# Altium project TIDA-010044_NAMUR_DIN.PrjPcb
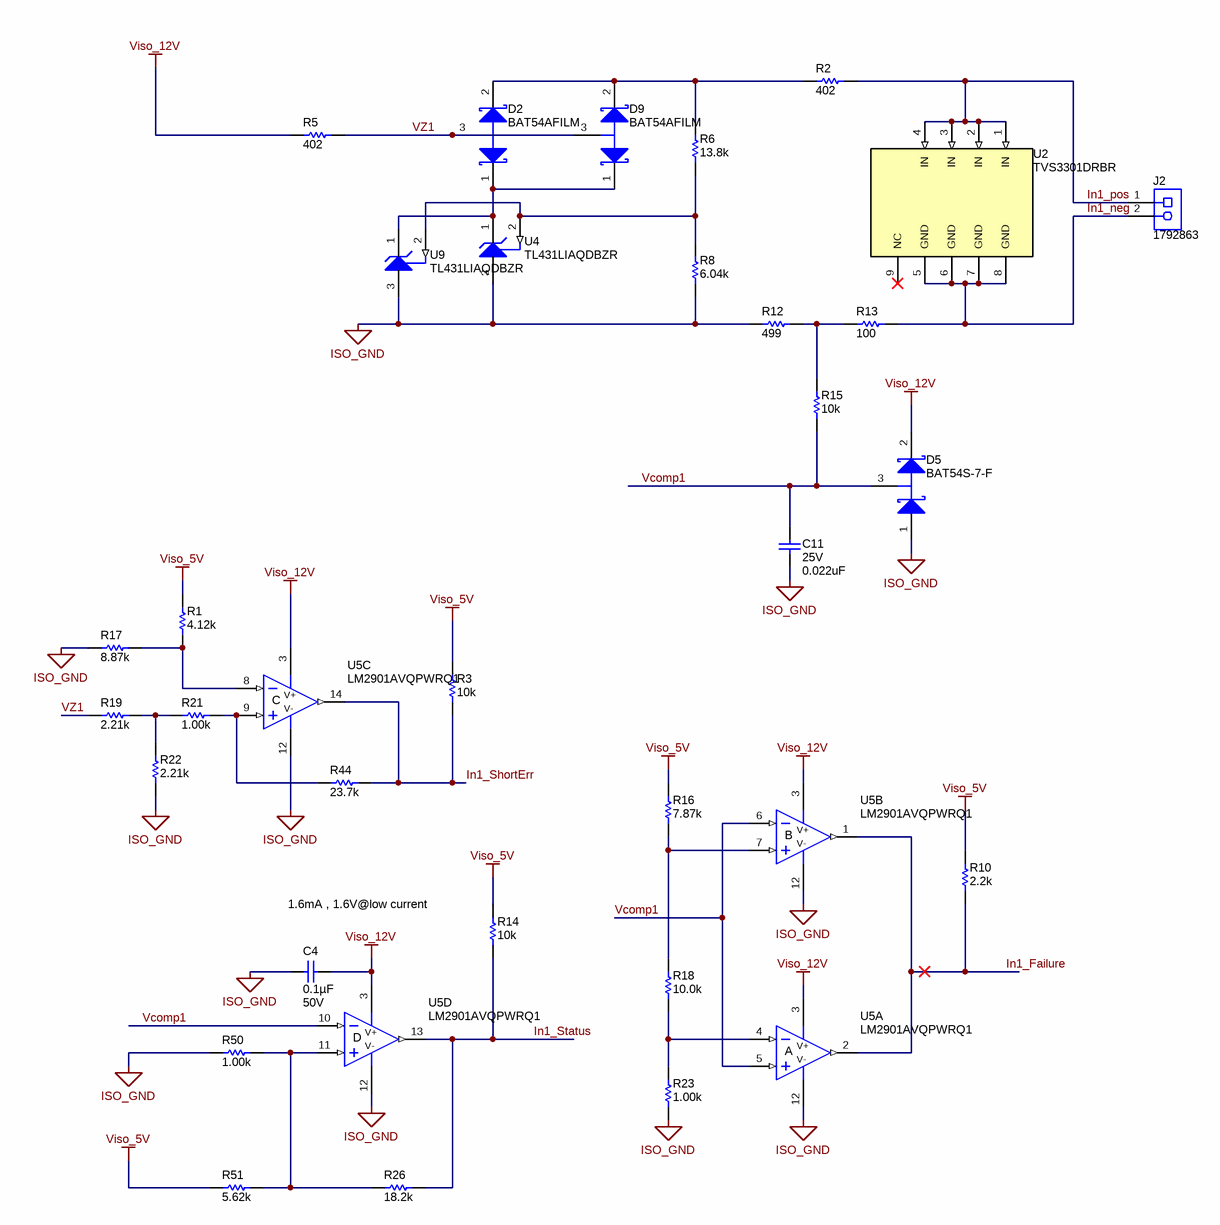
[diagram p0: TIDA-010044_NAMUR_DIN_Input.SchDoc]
CopyrightYear: 2018; PCB_Layout: Ahmed Noeman; PCB_Rev: A; PRJ_Customer: Public Release; PRJ_Engineer: Ahmed Noeman; PRJ_Number: TIDA-010044; PRJ_Title: NAMUR PLC digital input; SCH_Rev: A; TechSupport: http://www.ti.com/support; TID: TIDA-010044
4 sheets, 86 parts. Net scope: global (net labels, ports and power ports of the same name join across sheets).
Board file: TIDA-010044_NAMUR_DIN_PCB.PcbDoc
Sheets:
  TIDA-010044_NAMUR_DIN_Input.SchDoc
  TIDA-010044_NAMUR_DIN_CoverSheet.SchDoc
  TIDA-010044_NAMUR_DIN_Hardware.SchDoc
  TIDA-010044_NAMUR_DIN_Power.SchDoc

## Sheet TIDA-010044_NAMUR_DIN_Input.SchDoc: NAMUR DIN Input Stage
size 431 x 279 mm; Date: Not shown in title block; ApprovedBy: Not shown in title block; CheckedBy: Not shown in title block; Author: Not shown in title block; CompanyName: Not shown in title block; Engineer: Not shown in title block; Organization: Not shown in title block; Address1: Not shown in title block; Address2: Not shown in title block; Address3: Not shown in title block; Address4: Not shown in title block; DocumentNumber: 1; Revision: Use project parameter SCH_Rev; SheetNumber: 3; SheetTotal: 4; PageSetup: Record=PageOptions¦CenterHorizontal=True¦CenterVertical=True¦PrintScale=1.00¦XCorrection=1.00¦YCorrection=1.00¦PrintKind=0¦BorderSize=5000000¦LeftOffset=0¦BottomOffset=0¦Orientation=2¦PaperLength=1000¦PaperWidth=1000¦Scale=100¦PaperSource=15¦PrintQuality=600¦MediaType=1¦DitherType=10¦PaperKind=Letter¦PrintScaleMode=1

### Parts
C4  ValueDisplayed: 0.1µF  VDC_V: 50V  [0603]  (hidden comment: 06035C104JAT2A)
C11  VDC_V: 25V  ValueDisplayed: 0.022uF  [0603]  (hidden comment: C0603C223K3RACTU)
D2  BAT54AFILM  [SOT-23]
D5  BAT54S-7-F  [SOT-23]
D9  BAT54AFILM  [SOT-23]
J2  1792863  [Phoenix_1792863]
R1  ValueDisplayed: 4.12k  [0603]  (hidden comment: RT0603BRD074K12L)
R2  ValueDisplayed: 402  [MMB0207]  (hidden comment: MMB02070C4020FB200)
R3  ValueDisplayed: 10k  [0603]  (hidden comment: RC1608J103CS)
R5  ValueDisplayed: 402  [MMB0207]  (hidden comment: MMB02070C4020FB200)
R6  ValueDisplayed: 13.8k  [0603]  (hidden comment: RT0603BRD0713K8L)
R8  ValueDisplayed: 6.04k  [0603]  (hidden comment: RT0603DRE076K04L)
R10  ValueDisplayed: 2.2k  [0603]  (hidden comment: RC0603JR-072K2L)
R12  ValueDisplayed: 499  [MMB0207]  (hidden comment: MMB02070C4990FB200)
R13  ValueDisplayed: 100  [MMB0207]  (hidden comment: CMB02070X1000GB200)
R14  ValueDisplayed: 10k  [0603]  (hidden comment: RC1608J103CS)
R15  ValueDisplayed: 10k  [0603]  (hidden comment: RC1608J103CS)
R16  ValueDisplayed: 7.87k  [0603]  (hidden comment: RG1608P-7871-B-T5)
R17  ValueDisplayed: 8.87k  [0603]  (hidden comment: RT0603BRD078K87L)
R18  ValueDisplayed: 10.0k  [TNPW0603]  (hidden comment: TNPW060310K0BEEA)
R19  ValueDisplayed: 2.21k  [0603]  (hidden comment: RT0603BRD072K21L)
R21  ValueDisplayed: 1.00k  [0603]  (hidden comment: RT0603BRD071KL)
R22  ValueDisplayed: 2.21k  [0603]  (hidden comment: RT0603BRD072K21L)
R23  ValueDisplayed: 1.00k  [0603]  (hidden comment: RT0603BRD071KL)
R26  ValueDisplayed: 18.2k  [0603]  (hidden comment: ERA-3AEB1822V)
R44  ValueDisplayed: 23.7k  [0603]  (hidden comment: RC0603FR-0723K7L)
R50  ValueDisplayed: 1.00k  [0603]  (hidden comment: RT0603BRD071KL)
R51  ValueDisplayed: 5.62k  [0603]  (hidden comment: RT0603BRD075K62L)
U2  TVS3301DRBR  [DRB0008A]
U4  TL431LIAQDBZR  [DBZ0003A_N]
U5  LM2901AVQPWRQ1  [PW0014A_N]  (parts A,B,C,D of 4)
U9  TL431LIAQDBZR  [DBZ0003A_N]

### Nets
ISO_GND: C4.1 C11.2 D5.1(A) R8.1 R12.1 R17.2 R22.1 R23.1 R50.1 U4.3(ANODE) U5.12(V-) U9.3(ANODE)
Viso_5V: R1.2 R3.2 R10.2 R14.2 R16.2 R51.1
Viso_12V: C4.2 D5.2(K) R5.1 U5.3(V+)
In1_Failure: R10.1 U5.1(OUT2) U5.2(OUT1)
In1_neg: J2.2 R13.2 U2.5(GND) U2.6(GND) U2.7(GND) U2.8(GND)
In1_pos: J2.1 R2.2 U2.1(IN) U2.2(IN) U2.3(IN) U2.4(IN)
In1_ShortErr: R3.1 R44.2 U5.14(OUT3)
In1_Status: R14.1 R26.2 U5.13(OUT4)
Vcomp1: C11.1 D5.3(C) R15.1 U5.5(+IN1) U5.6(-IN2) U5.10(-IN4)
VZ1: D2.3(A) D9.3(A) R5.2 R19.2
NetD2_1: D2.1(K1) D9.1(K1) U4.1(CATHODE) U9.1(CATHODE)
NetD2_2: D2.2(K2) D9.2(K2) R2.1 R6.2
NetR1_1: R1.1 R17.1 U5.8(-IN3)
NetR6_1: R6.1 R8.2 U4.2(REF) U9.2(REF)
NetR12_2: R12.2 R13.1 R15.2
NetR16_1: R16.1 R18.2 U5.7(+IN2)
NetR18_1: R18.1 R23.2 U5.4(-IN1)
NetR19_1: R19.1 R21.1 R22.2
NetR21_2: R21.2 R44.1 U5.9(+IN3)
NetR26_1: R26.1 R50.2 R51.2 U5.11(+IN4)

Not connected (* = marked no-connect by the designer): U2 9(NC)*

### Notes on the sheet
- 1.6mA , 1.6V@low current

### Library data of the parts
C4 = CMP-0083854-1: CAP, CERM, 0.1 µF, 50 V,+/- 5%, X7R, 0603; Manufacturer: AVX; Polarized: N; Value: 0.1uF; U/M: EA; Cap_F: 100nF; TaMin_C: -55°C; TaMax_C: 125°C; AEC Category: Q200; Green_Lifecycle: Active; SizeAreaWB_mm2: 4.68; Green_REACh: Passed; SizeZ_mm: 1; SizeX_mm: 1.6; SizeY_mm: 0.8; SizeArea_mm2: 1.28
C11 = CMP-0006899-4: CAP, CERM, 0.022 uF, 25 V, +/- 10%, X7R, 0603; Manufacturer: Kemet; TaMin_C: -55°C; Polarized: N; SizeAreaWB_mm2: 4.68; Value1: Unknown; U/M: EA; TaMax_C: 125°C; SizeZ_mm: 1; SizeX_mm: 1.6; SizeY_mm: 0.8; SizeArea_mm2: 1.28; Cap_F: 22nF; AEC Category: Q200
D2 D9 = CMP-0028619-2: Diode, Schottky, 40 V, 0.3 A, SOT-23; Manufacturer: STMicroelectronics; Io_A: 3dA; Green_Lifecycle: Active; SizeAreaWB_mm2: 14; Vr_V: 40V; Green_REACh: Passed; Value1: 0.3A; TJmax_C: 150°C; Value: 40V; SizeZ_mm: 1.1; SizeX_mm: 2.5; SizeY_mm: 3; Vf_V: 9dV; Value2: 0.9V; SizeArea_mm2: 7.5; AEC Category: Q101
D5 = CMP-0028456-2: Diode, Schottky, 30 V, 0.2 A, SOT-23; Manufacturer: Diodes Inc.; Io_A: 2dA; Green_Lifecycle: Active; SizeAreaWB_mm2: 14; Vr_V: 30V; Green_REACh: Passed; Value1: 0.2A; TJmax_C: 125°C; Value: 30V; SizeZ_mm: 1.1; SizeX_mm: 2.5; SizeY_mm: 3; Vf_V: 6.5dV; Value2: 0.65V; SizeArea_mm2: 7.5; AEC Category: Q101
J2 = CMP-0055529-1: Terminal Block, 5mm, 2x1, R/A, TH; Manufacturer: Phoenix Contact; Pitch_mm: 5; Gender: Female; Row_Count: 1; Current_A: 16A; Voltage_V: 400V; Cert_UL: Y; CNHeader: FALSE; CT: TRUE
R1 = CMP-0024288-2: RES, 4.12 k, 0.1%, 0.1 W, 0603; Manufacturer: Yageo America; Power_W: 100mW; TempCo: 25 ppm/C; Value_Code: 4k12; U/M: EA; Value: 4.12k; EIA_Code: E192; SizeX_mm: 1.6; SizeY_mm: 0.8; SizeZ_mm: 1; Value2: 0.1W; SizeArea_mm2: 1.28; VDC_V: 75V; AEC Category: Q200
R2 R5 = CMP-0077149-1: RES, 402, 1%, 1 W, AEC-Q200 Grade 0, 2.2x5.8mm; Manufacturer: Vishay/Beyschlag; Value_Code: 402R; AEC Qualified: Y; AEC Category: Q200; Value: 402; EIA_Code: E96; TempCo: 50 ppm/C; AEC Grade: 0; Power_W: 1W; VDC_V: 350V; U/M: EA
R3 R14 R15 = CMP-0025945-3: RES, 10 k, 5%, 0.1 W, 0603; Manufacturer: Samsung Electro-Mechanics; Power_W: 100mW; TempCo: 100 ppm/C; Value_Code: 10k0; U/M: EA; Value: 10k; EIA_Code: E24; SizeX_mm: 1.6; SizeY_mm: 0.8; SizeZ_mm: 1; Value2: 0.1W; SizeArea_mm2: 1.28; AEC Qualified: N; VDC_V: 31V; AEC Category: Q200
R6 = CMP-0023734-2: RES, 13.8 k, 0.1%, 0.1 W, 0603; Manufacturer: Yageo America; Power_W: 100mW; TempCo: 25 ppm/C; Value_Code: 13k8; U/M: EA; Value: 13.8k; EIA_Code: E192; SizeX_mm: 1.6; SizeY_mm: 0.8; SizeZ_mm: 1; Value2: 0.1W; SizeArea_mm2: 1.28; VDC_V: 75V; AEC Category: Q200
R8 = CMP-0025513-2: RES, 6.04 k, 0.5%, 0.1 W, 0603; Manufacturer: Yageo America; Power_W: 100mW; TempCo: 50 ppm/C; Value_Code: 6k04; U/M: EA; Value: 6.04k; EIA_Code: E192; SizeX_mm: 1.6; SizeY_mm: 0.8; SizeZ_mm: 1; Value2: 0.1W; SizeArea_mm2: 1.28; VDC_V: 75V; AEC Category: Q200
R10 = CMP-0025906-5: RES, 2.2 k, 5%, 0.1 W, 0603; Manufacturer: Yageo; Power_W: 100mW; TempCo: 100 ppm/C; Value_Code: 2k20; Value: 2.2k; EIA_Code: E24; SizeX_mm: 1.6; SizeY_mm: 0.8; SizeZ_mm: 1; Value2: 0.1W; SizeArea_mm2: 1.28; AEC Qualified: N; VDC_V: 75V; AEC Category: Q200; SizeAreaWB_mm2: 4.68
R12 = CMP-0077150-1: RES, 499, 1%, 1 W, AEC-Q200 Grade 0, 2.2x5.8mm; Manufacturer: Vishay/Beyschlag; Value_Code: 499R; AEC Qualified: Y; AEC Category: Q200; Value: 499; EIA_Code: E96; TempCo: 50 ppm/C; AEC Grade: 0; Power_W: 1W; VDC_V: 350V; U/M: EA
R13 = CMP-0077148-1: RES, 100, 2%, 1 W, AEC-Q200 Grade 0, 2.2x5.8mm; Manufacturer: Vishay/Beyschlag; Value_Code: 100R; AEC Qualified: Y; AEC Category: Q200; Value: 100; TempCo: ppm/C; AEC Grade: 0; Power_W: 1W; VDC_V: 500V; U/M: EA
R16 = CMP-0023602-3: RES, 7.87 k, 0.1%, 0.1 W, 0603; Manufacturer: Susumu Co Ltd; Power_W: 100mW; TempCo: 25 ppm/C; Value_Code: 7k87; U/M: EA; Value: 7.87k; EIA_Code: E192; SizeX_mm: 1.6; SizeY_mm: 0.8; SizeZ_mm: 1; Value2: 0.1W; SizeArea_mm2: 1.28; VDC_V: 75V; AEC Category: Q200
R17 = CMP-0024525-1: RES, 8.87 k, 0.1%, 0.1 W, 0603; Manufacturer: Yageo America; Power_W: 100mW; TempCo: 25 ppm/C; Value_Code: 8k87; U/M: EA; Value: 8.87k; EIA_Code: E192; SizeX_mm: 1.6; SizeY_mm: 0.8; SizeZ_mm: 1; Value2: 0.1W; SizeArea_mm2: 1.28; VDC_V: 75V; AEC Category: Q200
R18 = CMP-0025686-1: RES, 10.0 k, 0.1%, 0.1 W, AEC-Q200 Grade 1, 0603; Manufacturer: Vishay-Dale; Power_W: 100mW; TempCo: 25 ppm/C; Value_Code: 10k0; U/M: EA; Value: 10.0k; EIA_Code: E192; Res_ohm: 10k; SizeX_mm: 1.6; SizeY_mm: 0.85; SizeZ_mm: 0.55; Value2: 0.1W; SizeArea_mm2: 1.36; AEC Qualified: Y; VDC_V: 75V; AEC Category: Q200; AEC Grade: 1
R19 R22 = CMP-0024063-3: RES, 2.21 k, 0.1%, 0.1 W, 0603; Manufacturer: Yageo America; Power_W: 100mW; TempCo: 25 ppm/C; Value_Code: 2k21; U/M: EA; Value: 2.21k; EIA_Code: E192; SizeX_mm: 1.6; SizeY_mm: 0.8; SizeZ_mm: 1; Value2: 0.1W; SizeArea_mm2: 1.28; VDC_V: 75V; AEC Category: Q200
R21 R23 R50 = CMP-0023919-1: RES, 1.00 k, 0.1%, 0.1 W, 0603; Manufacturer: Yageo America; Power_W: 100mW; TempCo: 25 ppm/C; Value_Code: 1k00; U/M: EA; Value: 1.00k; EIA_Code: E192; Res_ohm: 1k; SizeX_mm: 1.6; SizeY_mm: 0.8; SizeZ_mm: 1; Value2: 0.1W; SizeArea_mm2: 1.28; VDC_V: 75V; AEC Category: Q200
R26 = CMP-0023370-2: RES, 18.2 k, 0.1%, 0.1 W, AEC-Q200 Grade 0, 0603; Manufacturer: Panasonic; Power_W: 100mW; TempCo: 25 ppm/C; Value_Code: 18k2; U/M: EA; Value: 18.2k; EIA_Code: E192; SizeX_mm: 1.6; SizeY_mm: 0.8; SizeZ_mm: 1; Value2: 0.1W; SizeArea_mm2: 1.28; AEC Qualified: Y; VDC_V: 75V; AEC Grade: 0; AEC Category: Q200
R44 = CMP-0022934-5: RES, 23.7 k, 1%, 0.1 W, 0603; Manufacturer: Yageo; Power_W: 100mW; TempCo: 100 ppm/C; Value_Code: 23k7; Value: 23.7k; EIA_Code: E96; SizeX_mm: 1.6; SizeY_mm: 0.8; SizeZ_mm: 1; Value2: 0.1W; SizeArea_mm2: 1.28; AEC Qualified: N; VDC_V: 75V; AEC Category: Q200; SizeAreaWB_mm2: 4.68
R51 = CMP-0024374-1: RES, 5.62 k, 0.1%, 0.1 W, 0603; Manufacturer: Yageo America; Power_W: 100mW; TempCo: 25 ppm/C; Value_Code: 5k62; U/M: EA; Value: 5.62k; EIA_Code: E192; SizeX_mm: 1.6; SizeY_mm: 0.8; SizeZ_mm: 1; Value2: 0.1W; SizeArea_mm2: 1.28; VDC_V: 75V; AEC Category: Q200
U2 = CMP-0081715-3: 33 V Bidirectional Flat-Clamp Surge Protection Device, DRB0008A (VSON-8); Alternate PartNumber: TVS3301DRBT; Alternate Manufacturer: Texas Instruments; SizeZ_mm: 1.0; SizeX_mm: 3.0; AEC Category: Q200; SizeAreaWB_mm2: 16.0; CompType: IC; Rating: Catalog; SizeArea_mm2: 9.0; AEC Qualified: N
U4 U9 = CMP-0084728-1: Programmable Shunt Regulator with Optimized Reference Current, DBZ0003A (SOT-23-3); Manufacturer: Texas Instruments; AEC Qualified: N; SizeZ_mm: 1.12; CompType: IC; SizeY_mm: 3; AEC Category: Q200; SizeX_mm: 2.5; SizeAreaWB_mm2: 14; SizeArea_mm2: 7.5
U5 = CMP-0065405-1: Automotive Catalog Quad Differential Comparator, PW0014A (TSSOP-14); Alternate Manufacturer: Texas Instruments; SizeAreaWB_mm2: 58.8; U/M: EA; SizeZ_mm: 1.2; SizeX_mm: 6.4; SizeY_mm: 5.0; SizeArea_mm2: 32.0; CompType: IC

## Sheet TIDA-010044_NAMUR_DIN_CoverSheet.SchDoc
size 431 x 279 mm; Date: Not shown in title block; ApprovedBy: Not shown in title block; CheckedBy: Not shown in title block; Author: Not shown in title block; CompanyName: Not shown in title block; Engineer: Not shown in title block; Organization: Not shown in title block; Address1: Not shown in title block; Address2: Not shown in title block; Address3: Not shown in title block; Address4: Not shown in title block; DocumentNumber: 1; Revision: Use project parameter SCH_Rev; SheetNumber: 1; SheetTotal: 4; PageSetup: Record=PageOptions¦CenterHorizontal=True¦CenterVertical=True¦PrintScale=1.00¦XCorrection=1.00¦YCorrection=1.00¦PrintKind=0¦BorderSize=5000000¦LeftOffset=0¦BottomOffset=0¦Orientation=2¦PaperLength=1000¦PaperWidth=1000¦Scale=100¦PaperSource=15¦PrintQuality=600¦MediaType=1¦DitherType=10¦PaperKind=Letter¦PrintScaleMode=1
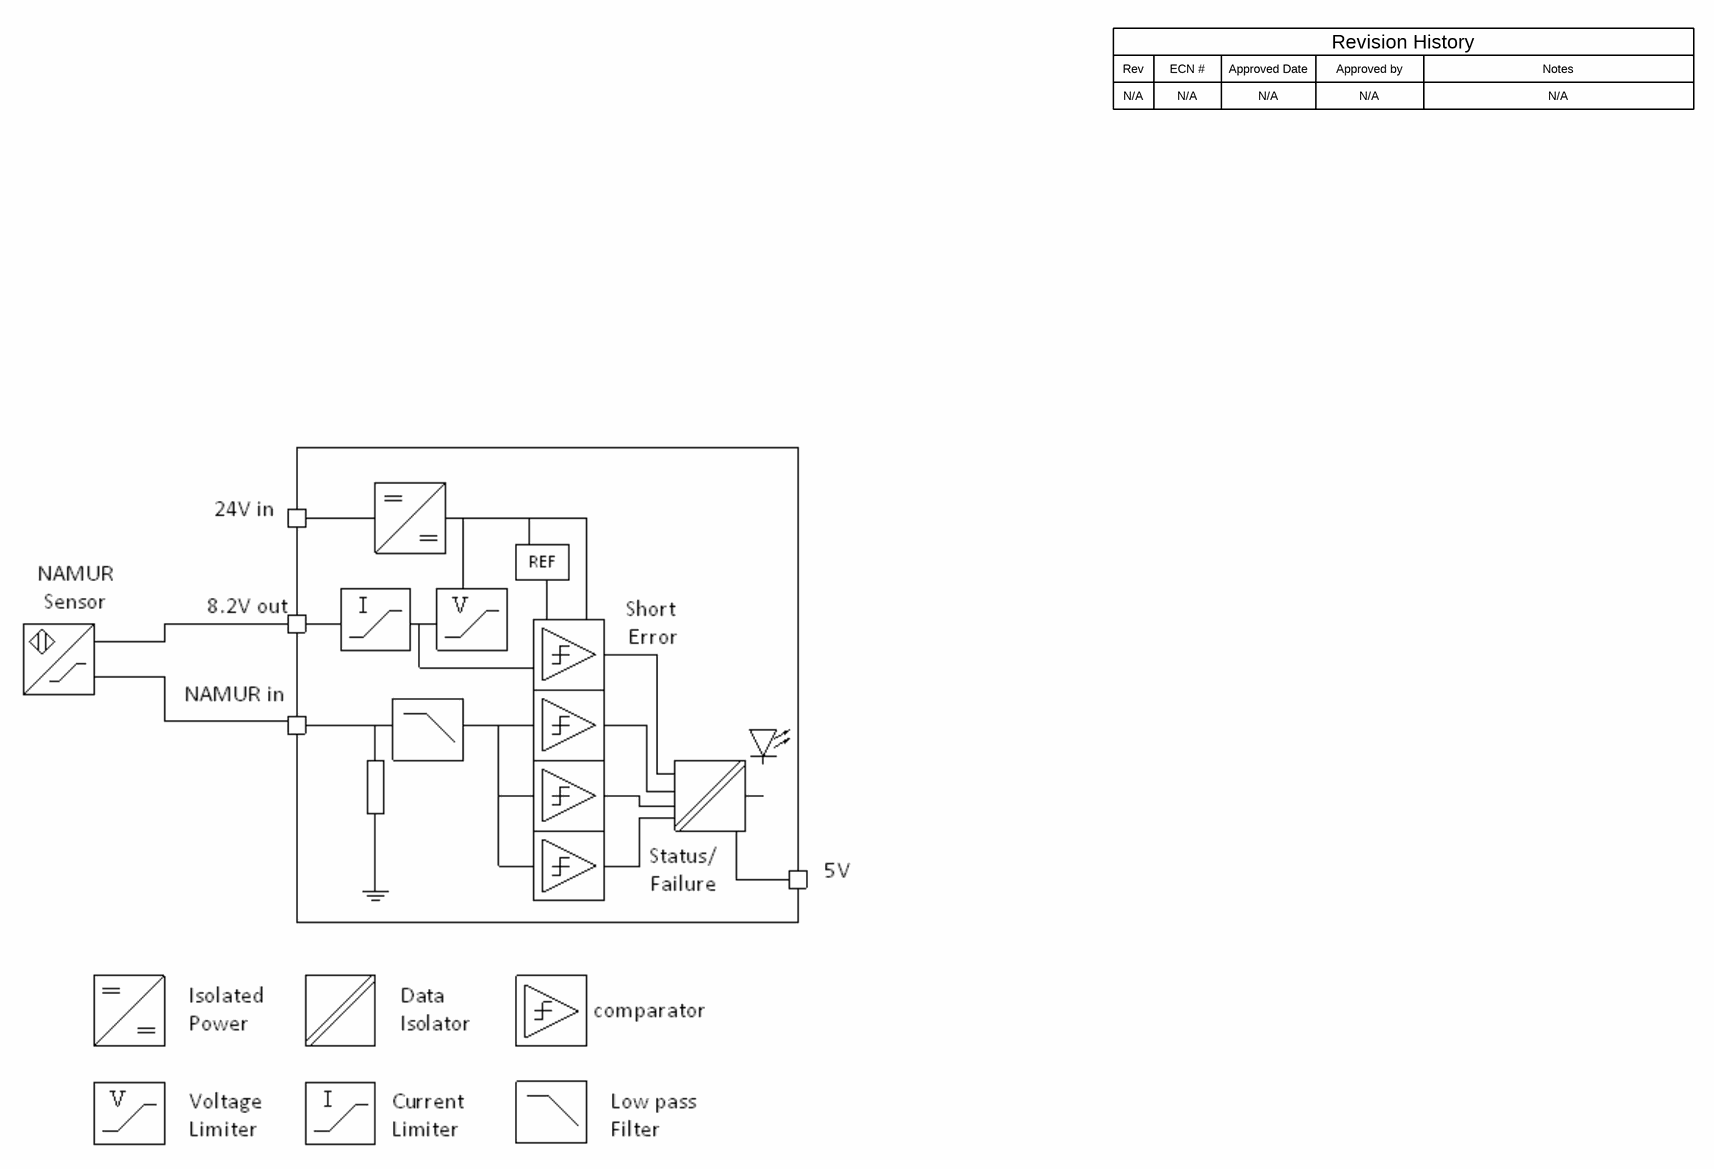
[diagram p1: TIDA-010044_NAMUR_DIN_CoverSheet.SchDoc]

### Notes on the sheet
- Rev
- N/A
- ECN #
- Approved Date
- Approved by
- Revision History
- Notes

## Sheet TIDA-010044_NAMUR_DIN_Hardware.SchDoc: Hardware
size 431 x 279 mm; Date: Not shown in title block; ApprovedBy: Not shown in title block; CheckedBy: Not shown in title block; Author: Not shown in title block; CompanyName: Not shown in title block; Engineer: Not shown in title block; Organization: Not shown in title block; Address1: Not shown in title block; Address2: Not shown in title block; Address3: Not shown in title block; Address4: Not shown in title block; DocumentNumber: 1; Revision: Use project parameter SCH_Rev; SheetNumber: 4; SheetTotal: 4; PageSetup: Record=PageOptions¦CenterHorizontal=True¦CenterVertical=True¦PrintScale=1.00¦XCorrection=1.00¦YCorrection=1.00¦PrintKind=0¦BorderSize=5000000¦LeftOffset=0¦BottomOffset=0¦Orientation=2¦PaperLength=1000¦PaperWidth=1000¦Scale=100¦PaperSource=15¦PrintQuality=600¦MediaType=1¦DitherType=10¦PaperKind=Letter¦PrintScaleMode=1
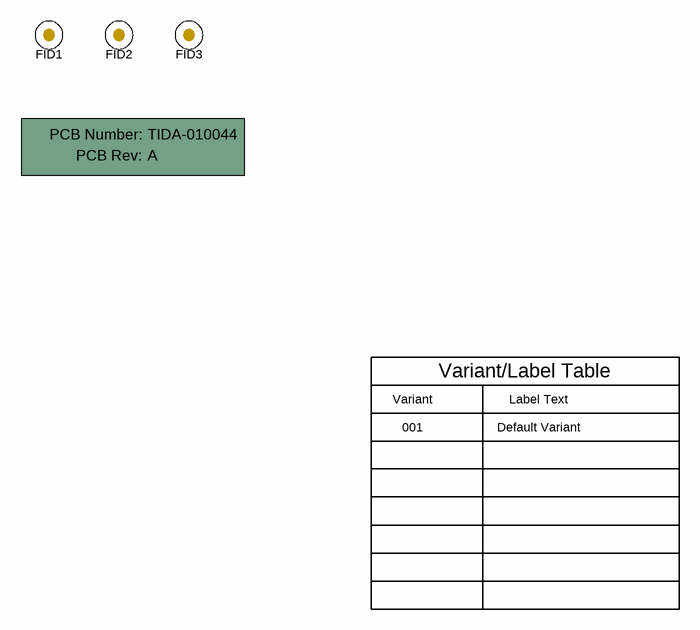
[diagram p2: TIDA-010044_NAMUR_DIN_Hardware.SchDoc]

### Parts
!PCB  Printed Circuit Board  (value not drawn)  (mechanical)
FID1  Fiducial  [Fiducial10-20]  (value not drawn)
FID2  Fiducial  [Fiducial10-20]  (value not drawn)
FID3  Fiducial  [Fiducial10-20]  (value not drawn)

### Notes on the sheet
- Variant
- Variant/Label Table
- Label Text
- 001
- Default Variant

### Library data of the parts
!PCB = PCB: Manufacturer: Any; PartNumber: TIDA-010044; SymbolCreator: a0412235
FID1-FID3 = CMP-0077181-1: Fiducial mark.  There is nothing to buy or mount.

## Sheet TIDA-010044_NAMUR_DIN_Power.SchDoc: NAMUR DIN Power Stage
size 431 x 279 mm; Date: Not shown in title block; ApprovedBy: Not shown in title block; CheckedBy: Not shown in title block; Author: Not shown in title block; CompanyName: Not shown in title block; DrawnBy: Ahmed Noeman; Engineer: Not shown in title block; Organization: Not shown in title block; Address1: Not shown in title block; Address2: Not shown in title block; Address3: Not shown in title block; Address4: Not shown in title block; DocumentNumber: 1; Revision: Use project parameter SCH_Rev; SheetNumber: 2; SheetTotal: 4; PageSetup: Record=PageOptions¦CenterHorizontal=True¦CenterVertical=True¦PrintScale=1.00¦XCorrection=1.00¦YCorrection=1.00¦PrintKind=0¦BorderSize=5000000¦LeftOffset=0¦BottomOffset=0¦Orientation=2¦PaperLength=1000¦PaperWidth=1000¦Scale=100¦PaperSource=15¦PrintQuality=600¦MediaType=1¦DitherType=10¦PaperKind=Letter¦PrintScaleMode=1
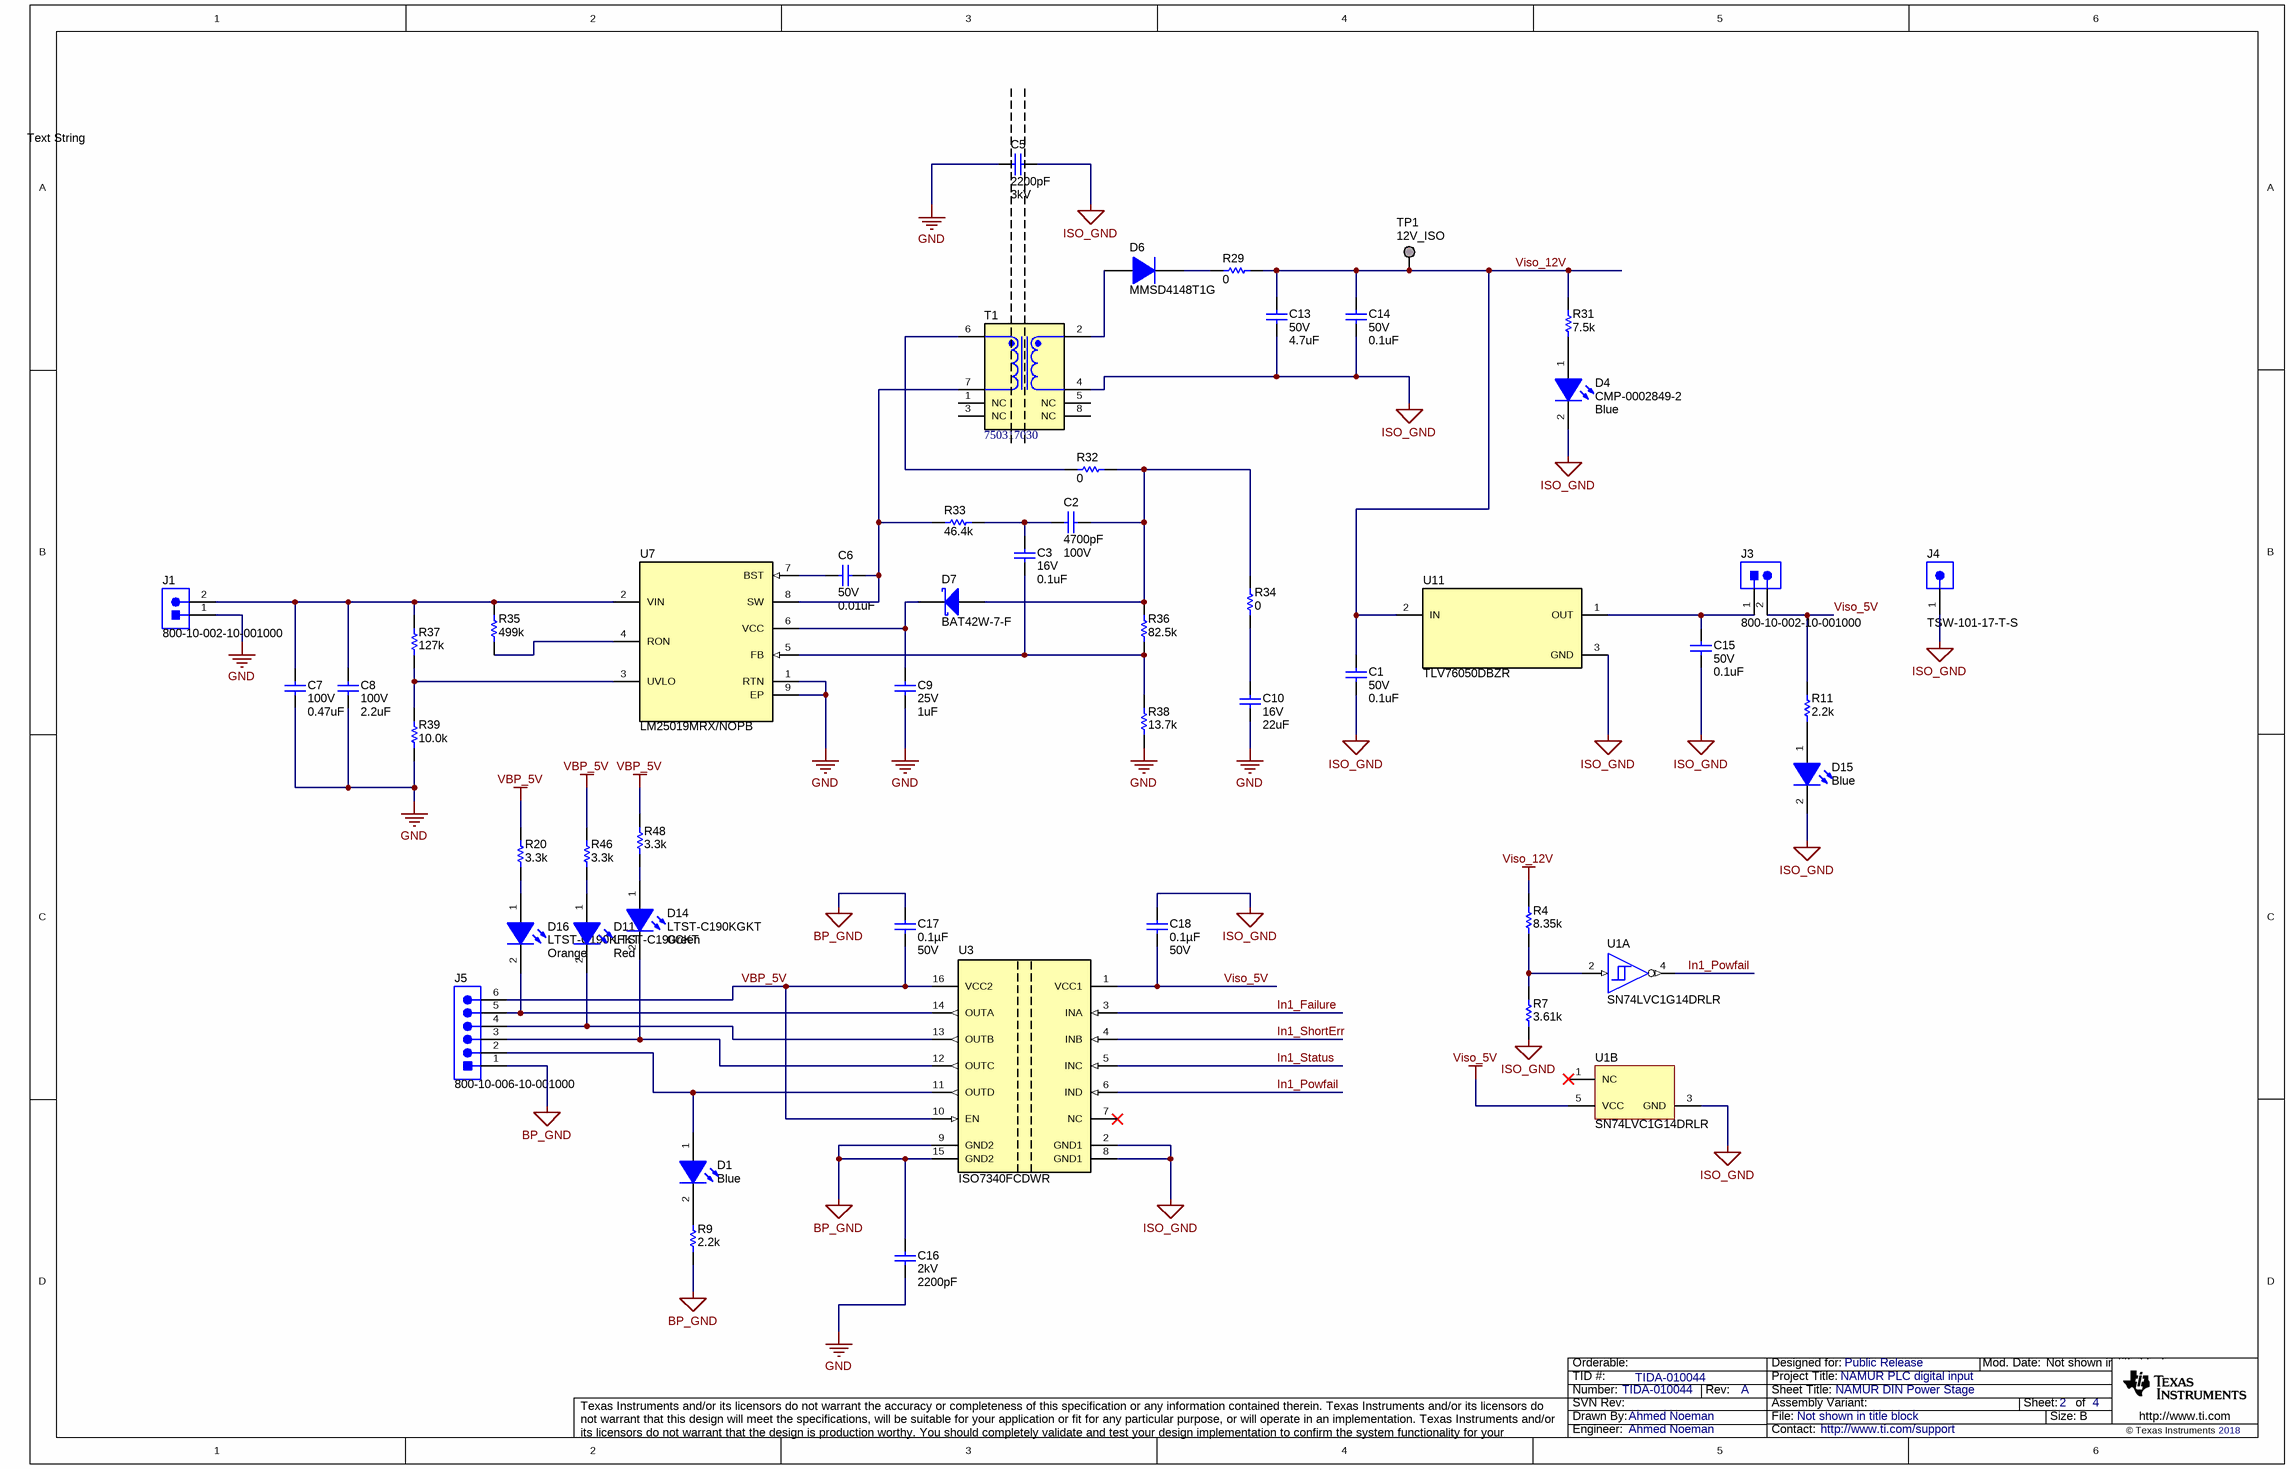
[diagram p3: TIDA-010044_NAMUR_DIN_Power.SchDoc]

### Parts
C1  VDC_V: 50V  ValueDisplayed: 0.1uF  [0805_HV]  (hidden comment: GCM21BR71H104KA37K)
C2  ValueDisplayed: 4700pF  VDC_V: 100V  [0603]  (hidden comment: CGA3E2X7R2A472K080AA)
C3  VDC_V: 16V  ValueDisplayed: 0.1uF  [0603]  (hidden comment: 0603YC104JAT2A)
C5  ValueDisplayed: 2200pF  VDC_V: 3kV  [1812_254]  (hidden comment: CMP-0009296-2)
C6  VDC_V: 50V  ValueDisplayed: 0.01uF  [0603]  (hidden comment: C0603C103J5RACTU)
C7  VDC_V: 100V  ValueDisplayed: 0.47uF  [1206_180]  (hidden comment: C3216X7R2A474K160AA)
C8  VDC_V: 100V  ValueDisplayed: 2.2uF  [1210]  (hidden comment: HMK325B7225KN-T)
C9  VDC_V: 25V  ValueDisplayed: 1uF  [0603]  (hidden comment: GRM188R71E105KA12D)
C10  VDC_V: 16V  ValueDisplayed: 22uF  [1210_280]  (hidden comment: GCM32ER71C226KE19L)
C13  VDC_V: 50V  ValueDisplayed: 4.7uF  [1206_180]  (hidden comment: GRM31CR71H475KA12L)
C14  VDC_V: 50V  ValueDisplayed: 0.1uF  [0805_HV]  (hidden comment: GCM21BR71H104KA37K)
C15  VDC_V: 50V  ValueDisplayed: 0.1uF  [0805_HV]  (hidden comment: GCM21BR71H104KA37K)
C16  VDC_V: 2kV  ValueDisplayed: 2200pF  [1210_280]  (hidden comment: 202S41W222KV4E)
C17  ValueDisplayed: 0.1µF  VDC_V: 50V  [0603]  (hidden comment: 06035C104JAT2A)
C18  ValueDisplayed: 0.1µF  VDC_V: 50V  [0603]  (hidden comment: 06035C104JAT2A)
D1  value Blue  [LB Q39G_BLUE]  (hidden comment: LB Q39G-L2N2-35-1)
D4  CMP-0002849-2  value Blue  [LB Q39G_BLUE]
D6  MMSD4148T1G  [SOD-123]
D7  BAT42W-7-F  [SOD-123]
D11  LTST-C190CKT  value Red  [LED_LTST-C190_Red]
D14  LTST-C190KGKT  value Green  [LED_LTST-C190_G]
D15  value Blue  [LB Q39G_BLUE]  (hidden comment: LB Q39G-L2N2-35-1)
D16  LTST-C190KFKT  value Orange  [LED_LTST-C190]
J1  800-10-002-10-001000  [Mill-Max_800-10-002-10-001000]
J3  800-10-002-10-001000  [Mill-Max_800-10-002-10-001000]
J4  TSW-101-17-T-S  [Samtec_TSW-101-17-T-S]
J5  800-10-006-10-001000  [Mill-Max_800-10-006-10-001000]
R4  ValueDisplayed: 8.35k  [PTN_0603]  (hidden comment: PTN0603E8351BST1)
R7  ValueDisplayed: 3.61k  [0603]  (hidden comment: RT0603BRD073K61L)
R9  ValueDisplayed: 2.2k  [0603]  (hidden comment: CMP-0025906-5)
R11  ValueDisplayed: 2.2k  [0603]  (hidden comment: CMP-0025906-5)
R20  ValueDisplayed: 3.3k  [0603]  (hidden comment: RC0603JR-073K3L)
R29  ValueDisplayed: 0  [0603]  (hidden comment: CMP-0025885-5)
R31  ValueDisplayed: 7.5k  [0603]  (hidden comment: RC0603JR-077K5L)
R32  ValueDisplayed: 0  [0603]  (hidden comment: CMP-0025885-5)
R33  ValueDisplayed: 46.4k  [0603]  (hidden comment: RC0603FR-0746K4L)
R34  ValueDisplayed: 0  [0603]  (hidden comment: CMP-0025885-5)
R35  ValueDisplayed: 499k  [0603]  (hidden comment: RC0603FR-07499KL)
R36  ValueDisplayed: 82.5k  [0603]  (hidden comment: CRCW060382K5FKEA)
R37  ValueDisplayed: 127k  [0603]  (hidden comment: CRCW0603127KFKEA)
R38  ValueDisplayed: 13.7k  [0603]  (hidden comment: CRCW060313K7FKEA)
R39  ValueDisplayed: 10.0k  [0603]  (hidden comment: ERJ-3EKF1002V)
R46  ValueDisplayed: 3.3k  [0603]  (hidden comment: RC0603JR-073K3L)
R48  ValueDisplayed: 3.3k  [0603]  (hidden comment: RC0603JR-073K3L)
T1  750317030  [Wurth_ER9_5S_6310]
TP1  12V_ISO  [Keystone1573-2]
U1  SN74LVC1G14DRLR  [DRL0005A]  (parts A,B of 2)
U3  ISO7340FCDWR  [DW0016B_HV]
U7  LM25019MRX/NOPB  [DDA0008B_N]
U11  TLV76050DBZR  [DBZ0003A_N]

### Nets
BP_GND: C16.1 C17.2 J5.1 R9.1 U3.9(GND2) U3.15(GND2)
GND: C5.1 C7.2 C8.2 C9.2 C10.2 C16.2 J1.1 R38.1 R39.1 U7.1(RTN) U7.9(EP)
ISO_GND: C1.2 C5.2 C13.2 C14.2 C15.2 C18.2 D4.2(K) D15.2(K) J4.1 R7.1 T1.4 U1.3(GND) U3.2(GND1) U3.8(GND1) U11.3(GND)
VBP_5V: C17.1 J5.6 R20.1 R46.1 R48.1 U3.10(EN) U3.16(VCC2)
Viso_5V: C18.1 J3.2 R11.2 U1.5(VCC) U3.1(VCC1)
Viso_12V: C1.1 C13.1 C14.1 R4.2 R29.2 R31.2 TP1.1 U11.2(IN)
In1_Failure: U3.3(INA)
In1_Powfail: U1.4(Y) U3.6(IND)
In1_ShortErr: U3.4(INB)
In1_Status: U3.5(INC)
NetC2_1: C2.1 D7.2(A) R32.2 R34.2 R36.2
NetC2_2: C2.2 C3.1 R33.2
NetC3_2: C3.2 R36.1 R38.2 U7.5(FB)
NetC6_1: C6.1 R33.1 T1.7 U7.8(SW)
NetC6_2: C6.2 U7.7(BST)
NetC7_1: C7.1 C8.1 J1.2 R35.2 R37.2 U7.2(VIN)
NetC9_1: C9.1 D7.1(K) U7.6(VCC)
NetC10_1: C10.1 R34.1
NetC15_1: C15.1 J3.1 U11.1(OUT)
NetD1_1: D1.1(A) J5.2 U3.11(OUTD)
NetD1_2: D1.2(K) R9.2
NetD4_1: D4.1(A) R31.1
NetD6_1: D6.1(K) R29.1
NetD6_2: D6.2(A) T1.2
NetD11_1: D11.1(A) R46.2
NetD11_2: D11.2(K) J5.4 U3.13(OUTB)
NetD14_1: D14.1(A) R48.2
NetD14_2: D14.2(K) J5.3 U3.12(OUTC)
NetD15_1: D15.1(A) R11.1
NetD16_1: D16.1(A) R20.2
NetD16_2: D16.2(K) J5.5 U3.14(OUTA)
NetR4_1: R4.1 R7.2 U1.2(A)
NetR32_1: R32.1 T1.6
NetR35_1: R35.1 U7.4(RON)
NetR37_1: R37.1 R39.2 U7.3(UVLO)

Not connected (* = marked no-connect by the designer): T1 1(NC) 3(NC) 5(NC) 8(NC); U1 1(NC)*; U3 7(NC)*

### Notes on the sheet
- Text String

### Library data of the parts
C1 C14 C15 = CMP-0008021-2: CAP, CERM, 0.1 uF, 50 V, +/- 10%, X7R, AEC-Q200 Grade 1, 0805; Manufacturer: MuRata; TaMin_C: -55°C; Polarized: N; SizeAreaWB_mm2: 6.75; Value1: Unknown; U/M: EA; Value: 0.1uF; TaMax_C: 125°C; SizeZ_mm: 1.45; SizeX_mm: 2; SizeY_mm: 1.25; Cap_Case: 0805; SizeArea_mm2: 2.5; AEC Qualified: Y; AEC Grade: 1; AEC Category: Q200; Cap_F: 100nF
C2 = CMP-0007088-4: CAP, CERM, 4700 pF, 100 V, +/- 10%, X7R, AEC-Q200 Grade 1, 0603; Manufacturer: TDK; Polarized: N; Value: 4700pF; U/M: EA; Cap_F: 4.7nF; ESR_ohm: 4.69862d; Value1: 0.469862 ohm; IRMS_A: 3.2335dA; TaMin_C: -55°C; TaMax_C: 125°C; SizeArea_mm2: 1.28; SizeAreaWB_mm2: 4.68; SizeX_mm: 1.6; SizeY_mm: 0.8; SizeZ_mm: 1; AEC Category: Q200; AEC Qualified: Y
C3 = CMP-0006808-4: CAP, CERM, 0.1 uF, 16 V, +/- 5%, X7R, 0603; Manufacturer: AVX; TaMin_C: -55°C; ESR_ohm: 0.039; Polarized: N; SizeAreaWB_mm2: 4.68; Value1: 0.039 ohm; U/M: EA; Value: 0.1uF; TaMax_C: 125°C; SizeZ_mm: 1; SizeX_mm: 1.6; SizeY_mm: 0.8; SizeArea_mm2: 1.28; Cap_F: 100nF; AEC Category: Q200
C5 = CMP-0009296-2: CAP, CERM, 2200 pF, 3000 V, +/- 10%, X7R, 1812; PartNumber: 1812HC222KAT1A; Manufacturer: AVX; Polarized: N; Value: 2200pF; U/M: EA; Cap_F: 2.2nF; Value1: Unknown; Value2: 3000V; TaMin_C: -55°C; TaMax_C: 125°C; Cap_Case: 1812; AEC Category: Q200; SizeAreaWB_mm2: 23.1; SizeZ_mm: 2.54; SizeX_mm: 4.5; SizeY_mm: 3.2; SizeArea_mm2: 14.4
C6 = CMP-0006850-4: CAP, CERM, 0.01 uF, 50 V, +/- 5%, X7R, 0603; Manufacturer: Kemet; TaMin_C: -55°C; Polarized: N; SizeAreaWB_mm2: 4.68; Value1: Unknown; U/M: EA; Value: 0.01uF; TaMax_C: 125°C; SizeZ_mm: 1; SizeX_mm: 1.6; SizeY_mm: 0.8; SizeArea_mm2: 1.28; Cap_F: 10nF; AEC Category: Q200
C7 = CMP-0008716-2: CAP, CERM, 0.47 uF, 100 V, +/- 10%, X7R, 1206; Manufacturer: TDK; TaMin_C: -55°C; Polarized: N; SizeAreaWB_mm2: 10.92; Value1: 0.007558 ohm; U/M: EA; Value: 0.47uF; TaMax_C: 125°C; SizeZ_mm: 1.8; SizeX_mm: 3.2; SizeY_mm: 1.6; SizeArea_mm2: 5.12; Cap_F: 470nF; AEC Category: Q200; ESR_ohm: 7.558m; IRMS_A: 2.64716A
C8 = CMP-0009253-2: CAP, CERM, 2.2 uF, 100 V, +/- 10%, X7R, 1210; Manufacturer: Taiyo Yuden; TaMin_C: -55°C; Polarized: N; SizeAreaWB_mm2: 14.7; Value1: Unknown; U/M: EA; Value: 2.2uF; TaMax_C: 125°C; SizeZ_mm: 1.35; SizeX_mm: 3.2; SizeY_mm: 2.5; SizeArea_mm2: 8; Cap_F: 2.2µF; AEC Category: Q200
C9 = CMP-0007405-4: CAP, CERM, 1 uF, 25 V, +/- 10%, X7R, 0603; Manufacturer: MuRata; TaMin_C: -55°C; Polarized: N; SizeAreaWB_mm2: 4.68; Value1: Unknown; U/M: EA; Value: 1uF; TaMax_C: 125°C; SizeZ_mm: 1; SizeX_mm: 1.6; SizeY_mm: 0.8; SizeArea_mm2: 1.28; Cap_F: 1µF; AEC Category: Q200
C10 = CMP-0009174-2: CAP, CERM, 22 uF, 16 V, +/- 10%, X7R, 1210; Manufacturer: MuRata; TaMin_C: -55°C; Polarized: N; SizeAreaWB_mm2: 14.7; Value1: Unknown; U/M: EA; Value: 22uF; TaMax_C: 125°C; SizeZ_mm: 2.8; SizeX_mm: 3.2; SizeY_mm: 2.5; Cap_Case: 1210; SizeArea_mm2: 8; Cap_F: 22µF; AEC Category: Q200
C13 = CMP-0008969-2: CAP, CERM, 4.7 uF, 50 V, +/- 10%, X7R, 1206; Manufacturer: MuRata; TaMin_C: -55°C; Polarized: N; SizeAreaWB_mm2: 10.92; Value1: Unknown; U/M: EA; Value: 4.7uF; TaMax_C: 125°C; SizeZ_mm: 1.8; SizeX_mm: 3.2; SizeY_mm: 1.6; Cap_Case: 2220; SizeArea_mm2: 5.12; Cap_F: 4.7µF; AEC Category: Q200
C16 = CMP-0009070-1: CAP, CERM, 2200 pF, 2000 V, +/- 10%, X7R, 1210; Manufacturer: Johanson Technology; TaMin_C: -55°C; Polarized: N; SizeAreaWB_mm2: 14.7; Value1: Unknown; U/M: EA; Value: 2200pF; TaMax_C: 125°C; SizeZ_mm: 2.8; SizeX_mm: 3.2; SizeY_mm: 2.5; Cap_Case: 1210; Value2: 2000V; SizeArea_mm2: 8; Cap_F: 2.2nF; AEC Category: Q200
C17 C18 = CMP-0083854-1: as C4 on sheet TIDA-010044_NAMUR_DIN_Input
D1 D15 = CMP-0002849-2: LED, Blue, SMD; Manufacturer: OSRAM; Vf_V: 2.85V; Io_A: 1.5dA; Tjmax_C: 95°C; Value1: W
D4 = CMP-0002849-2: LED, Blue, SMD; Manufacturer: OSRAM; PartNumber: LB Q39G-L2N2-35-1; Vf_V: 2.85V; Io_A: 1.5dA; Tjmax_C: 95°C; Value1: W
D6 = CMP-0029032-2: Diode, Switching, 100 V, 0.2 A, SOD-123; Manufacturer: ON Semiconductor; Io_A: 2dA; Green_Lifecycle: Active; SizeAreaWB_mm2: 13.095; Vr_V: 100V; Green_REACh: Passed; Value1: 0.2A; TJmax_C: 150°C; Value: 100V; SizeZ_mm: 1.35; SizeX_mm: 3.85; SizeY_mm: 1.7; Vf_V: 1V; SizeArea_mm2: 6.545; AEC Category: Q101
D7 = CMP-0028446-2: Diode, Schottky, 30 V, 0.2 A, SOD-123; Manufacturer: Diodes Inc.; Io_A: 2dA; Green_Lifecycle: Not Set; SizeAreaWB_mm2: 13.095; Vr_V: 30V; Green_REACh: Incomplete; Value1: 0.2A; Value: 30V; SizeZ_mm: 1.35; SizeX_mm: 3.85; SizeY_mm: 1.7; Vf_V: 1V; SizeArea_mm2: 6.545; AEC Category: Q101
D11 = CMP-0002842-2: LED, Red, SMD; Manufacturer: Lite-On; Vf_V: 2V; Io_A: 20mA; Tjmax_C: 85°C; Power_TotalModule: 62.5mW; Value1: 0.0625W
D14 = CMP-0002840-2: LED, Green, SMD; Manufacturer: Lite-On; Type: AlInGaP; Vf_V: 2V; Io_A: 30mA; Tjmax_C: 85°C; Value1: W
D16 = CMP-0002826-2: LED, Orange, SMD; Manufacturer: Lite-On; Type: AlInGaP; Vf_V: 2V; Io_A: 20mA; Power_TotalModule: 75mW; Value1: 0.075W; U/M: EA
J1 J3 = CMP-0055085-1: Header, 100mil, 2x1, TH; Manufacturer: Mill-Max; CNHeader: TRUE; Green_Lifecycle: Active; Green_REACh: Passed; CT: FALSE
J4 = CMP-0055993-1: Header, 100mil, 1x1, Tin, TH; Manufacturer: Samtec; Cert_VDE: N; CNHeader: FALSE; Current_A: 6.3A; Green_Lifecycle: Active; Gender: Male; Cert_CSA: Y; Green_REACh: Passed; Voltage_V: 550V; Row_Count: 1; Pitch_mm: 2.54
J5 = CMP-0055084-1: Header, 100mil, 6x1, TH; Manufacturer: Mill-Max; CNHeader: TRUE; CT: FALSE
R4 = CMP-0080036-2: RES, 8.35 k, 0.1%, 0.15 W, Body 64x32mil; Manufacturer: Vishay Thin Film; Power_W: 150mW; TempCo: 25 ppm/C; Value_Code: 8k35; Value: 8.35k; EIA_Code: E192; SizeX_mm: 1.63; SizeY_mm: 0.81; SizeZ_mm: 0.508; Value2: 0.15W; SizeArea_mm2: 1.3203; AEC Qualified: N; VDC_V: 75V; AEC Category: Q200; SizeAreaWB_mm2: 4.7603
R7 = CMP-0024201-2: RES, 3.61 k, 0.1%, 0.1 W, 0603; Manufacturer: Yageo America; Power_W: 100mW; TempCo: 25 ppm/C; Value_Code: 3k61; U/M: EA; Value: 3.61k; EIA_Code: E192; SizeX_mm: 1.6; SizeY_mm: 0.8; SizeZ_mm: 1; Value2: 0.1W; SizeArea_mm2: 1.28; VDC_V: 75V; AEC Category: Q200
R9 = CMP-0025906-5: RES, 2.2 k, 5%, 0.1 W, 0603; PartNumber: RC0603JR-072K2L; Manufacturer: Yageo; CompType: Resistor; Value: 2.2k; Value_Code: 2k20; Power_W: 100mW; Value2: 0.1W; VDC_V: 75V; TempCo: 100 ppm/C; SizeArea_mm2: 1.28; SizeX_mm: 1.6; SizeY_mm: 0.8; SizeZ_mm: 1; EIA_Code: E24; AEC Category: Q200; AEC Qualified: N; SizeAreaWB_mm2: 4.68
R11 = CMP-0025906-5: RES, 2.2 k, 5%, 0.1 W, 0603; PartNumber: RC0603JR-072K2L; Manufacturer: Yageo; Value: 2.2k; Value_Code: 2k20; Power_W: 100mW; Value2: 0.1W; VDC_V: 75V; TempCo: 100 ppm/C; SizeArea_mm2: 1.28; SizeX_mm: 1.6; SizeY_mm: 0.8; SizeZ_mm: 1; EIA_Code: E24; AEC Category: Q200; AEC Qualified: N; SizeAreaWB_mm2: 4.68
R20 R46 R48 = CMP-0025918-5: RES, 3.3 k, 5%, 0.1 W, 0603; Manufacturer: Yageo; Value: 3.3k; Value_Code: 3k30; Power_W: 100mW; Value2: 0.1W; VDC_V: 75V; TempCo: 100 ppm/C; SizeArea_mm2: 1.28; SizeX_mm: 1.6; SizeY_mm: 0.8; SizeZ_mm: 1; EIA_Code: E24; AEC Category: Q200; AEC Qualified: N; SizeAreaWB_mm2: 4.68
R29 R32 R34 = CMP-0025885-5: RES, 0, 5%, 0.1 W, 0603; PartNumber: RC0603JR-070RL; Manufacturer: Yageo; Value: 0; Value_Code: 0000; Power_W: 100mW; Value2: 0.1W; VDC_V: 75V; TempCo: 200 ppm/C; SizeArea_mm2: 1.28; SizeX_mm: 1.6; SizeY_mm: 0.8; SizeZ_mm: 1; EIA_Code: E24; AEC Category: Q200; AEC Qualified: N; SizeAreaWB_mm2: 4.68
R31 = CMP-0025940-5: RES, 7.5 k, 5%, 0.1 W, 0603; Manufacturer: Yageo; Power_W: 100mW; TempCo: 100 ppm/C; Value_Code: 7k50; Value: 7.5k; EIA_Code: E24; SizeX_mm: 1.6; SizeY_mm: 0.8; SizeZ_mm: 1; Value2: 0.1W; SizeArea_mm2: 1.28; AEC Qualified: N; VDC_V: 75V; AEC Category: Q200; SizeAreaWB_mm2: 4.68
R33 = CMP-0023126-5: RES, 46.4 k, 1%, 0.1 W, 0603; Manufacturer: Yageo; Power_W: 100mW; TempCo: 100 ppm/C; Value_Code: 46k4; Value: 46.4k; EIA_Code: E96; SizeX_mm: 1.6; SizeY_mm: 0.8; SizeZ_mm: 1; Value2: 0.1W; SizeArea_mm2: 1.28; AEC Qualified: N; VDC_V: 75V; AEC Category: Q200; SizeAreaWB_mm2: 4.68
R35 = CMP-0023140-4: RES, 499 k, 1%, 0.1 W, 0603; Manufacturer: Yageo; Power_W: 100mW; TempCo: 100 ppm/C; Value: 499k; EIA_Code: E96; SizeX_mm: 1.6; SizeY_mm: 0.8; SizeZ_mm: 1; Value2: 0.1W; SizeArea_mm2: 1.28; AEC Qualified: N; VDC_V: 75V; AEC Category: Q200; SizeAreaWB_mm2: 4.68
R36 = CMP-0022620-2: RES, 82.5 k, 1%, 0.1 W, 0603; Manufacturer: Vishay-Dale; Power_W: 100mW; TempCo: 100 ppm/C; Value_Code: 82k5; U/M: EA; Value: 82.5k; EIA_Code: E96; SizeX_mm: 1.6; SizeY_mm: 0.8; SizeZ_mm: 1; Value2: 0.1W; SizeArea_mm2: 1.28; VDC_V: 75V; AEC Category: Q200
R37 = CMP-0022028-4: RES, 127 k, 1%, 0.1 W, AEC-Q200 Grade 0, 0603; Manufacturer: Vishay-Dale; Power_W: 100mW; TempCo: 100 ppm/C; Value: 127k; EIA_Code: E96; SizeX_mm: 1.6; SizeY_mm: 0.8; SizeZ_mm: 1; Value2: 0.1W; SizeArea_mm2: 1.28; AEC Qualified: Y; VDC_V: 75V; AEC Category: Q200; AEC Grade: 0
R38 = CMP-0022044-2: RES, 13.7 k, 1%, 0.1 W, 0603; Manufacturer: Vishay-Dale; Power_W: 100mW; TempCo: 100 ppm/C; Value_Code: 13k7; U/M: EA; Value: 13.7k; EIA_Code: E96; SizeX_mm: 1.6; SizeY_mm: 0.8; SizeZ_mm: 1; Value2: 0.1W; SizeArea_mm2: 1.28; VDC_V: 75V; AEC Category: Q200
R39 = CMP-0022684-2: RES, 10.0 k, 1%, 0.1 W, 0603; Manufacturer: Panasonic; Power_W: 100mW; TempCo: 100 ppm/C; Value_Code: 10k0; U/M: EA; Value: 10.0k; EIA_Code: E96; Res_ohm: 10k; SizeX_mm: 1.6; SizeY_mm: 0.8; SizeZ_mm: 1; Value2: 0.1W; SizeArea_mm2: 1.28; VDC_V: 75V; AEC Category: Q200
T1 = CMP-0077153-3: Transformer, 80 uH, SMT; Manufacturer: Wurth Elektronik; SizeAreaWB_mm2: 192.0; SizeArea_mm2: 140.0; AEC Qualified: N; Lp: 80.0; AEC Category: Q200; Value: 80uH; SizeZ_mm: 5.0; Ind_H: 80µH; SizeY_mm: 10.0; Ns1toNp: 1.39; LeakageInd_H: 1µH; Rsec1_ohm: 5d; DCR_ohm: 3.1d; SizeX_mm: 14.0
TP1 = CMP-0055119-1: Terminal, Turret, TH, Double; PartNumber: 1573-2; Manufacturer: Keystone; CompType: Turret Terminal; CNHeader: FALSE; Green_Lifecycle: Active; Green_REACh: Passed
U1 = CMP-0051645-2: Single Schmitt-Trigger Inverter, DRL0005A, LARGE T&R; Manufacturer: Texas Instruments; Rating: Catalog; ICC @ Nom Voltage(Max)(mA): 0.01; 3-State Output: No; Input Type: CMOS/TTL; Voltage(Nom)(V): 1.8,2.5,3.3,5; VCC(Min)(V): 1.65; F @ Nom Voltage(Max)(Mhz): 150; Sub-Family: Inverting Buffer/Driver; VCC(Max)(V): 5.5; tpd @ Nom Voltage(Max)(ns): 11,6.5,5.5,5; Output Type: CMOS; Output Drive (IOL/IOH)(Max)(mA): 32/-32; Schmitt Trigger: Yes; Technology Family: LVC; Logic: Inverting; Bits(#): 1; AEC Category: Q200; AEC Qualified: N; CompType: IC; SizeArea_mm2: 2.56; SizeX_mm: 1.6; SizeZ_mm: 0.6
U3 = CMP-0065832-2: Robust EMC, Low Power, Quad-Channel 4/0 Digital Isolator, Fail-Safe Low, DW0016B (SOIC-16); Manufacturer: Texas Instruments; SizeZ_mm: 2.65; SizeX_mm: 10.4; SizeY_mm: 10.3; SizeArea_mm2: 107.12; CompType: IC; U/M: EA; SizeAreaWB_mm2: 152.52
U7 = CMP-0066058-2: 7.5-48V Wide Vin, 100mA Constant On-Time Synchronous Buck Regulator, DDA0008B (SOIC-8); Manufacturer: Texas Instruments; Alternate PartNumber: LM25019MR/NOPB; SizeX_mm: 5.0; SizeY_mm: 6.2; CompType: IC; SizeZ_mm: 1.7; SizeArea_mm2: 31.0; SizeAreaWB_mm2: 57.4; U/M: EA
U11 = CMP-0074892-1: 100-mA, 30-V, Fixed-Output, Linear-Voltage Regulator, DBZ0003A (SOT-23-3); Alternate PartNumber: TLV76050DBZT; Alternate Manufacturer: Texas Instruments; SizeAreaWB_mm2: 14.0; SizeZ_mm: 1.12; SizeX_mm: 2.5; SizeY_mm: 3.0; SizeArea_mm2: 7.5; CompType: IC; AEC Qualified: N; AEC Category: Q200

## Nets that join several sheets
ISO_GND: TIDA-010044_NAMUR_DIN_Input (12 pins), TIDA-010044_NAMUR_DIN_Power (15 pins)
Viso_5V: TIDA-010044_NAMUR_DIN_Input (6 pins), TIDA-010044_NAMUR_DIN_Power (5 pins)
Viso_12V: TIDA-010044_NAMUR_DIN_Input (C4.2 D5.2 R5.1 U5.3), TIDA-010044_NAMUR_DIN_Power (8 pins)
In1_Failure: TIDA-010044_NAMUR_DIN_Input (R10.1 U5.1 U5.2), TIDA-010044_NAMUR_DIN_Power (U3.3)
In1_ShortErr: TIDA-010044_NAMUR_DIN_Input (R3.1 R44.2 U5.14), TIDA-010044_NAMUR_DIN_Power (U3.4)
In1_Status: TIDA-010044_NAMUR_DIN_Input (R14.1 R26.2 U5.13), TIDA-010044_NAMUR_DIN_Power (U3.5)

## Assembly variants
001: not fitted C11 FID1 FID2 FID3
